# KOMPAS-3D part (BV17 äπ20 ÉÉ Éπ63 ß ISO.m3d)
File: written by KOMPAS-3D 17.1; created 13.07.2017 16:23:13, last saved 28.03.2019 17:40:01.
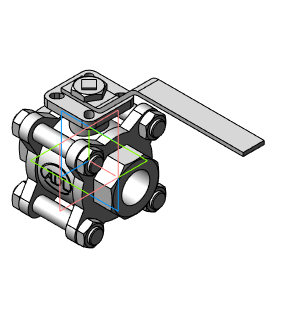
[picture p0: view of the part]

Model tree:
1. Операция без истории:2  (labels: Сталь 20  ГОСТ 1050-88)

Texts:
  DISO1
  DISO2
  BV17 Ду8 1/4" Ру63 с ISO
  BV17 Ду8 СС Ру63 с ISO
  BV17 Ду10 3/8" Ру63 с ISO
  BV17 Ду10 СС Ру63 с ISO
  BV17 Ду15 1/2" Ру63 с ISO
  BV17 Ду15 СС Ру63 с ISO
  BV17 Ду15 ФФ Ру40 с ISO
  BV17 Ду20 3/4" Ру63 с ISO
  BV17 Ду20 СС Ру40 с ISO
  BV17 Ду20 ФФ Ру40 с ISO
  BV17 Ду25 1" Ру63 с ISO
  BV17 Ду25 СС Ру63 с ISO
  BV17 Ду25 ФФ Ру40 с ISO
  BV17 Ду32 1 1/4" Ру63 с ISO
  BV17 Ду32 СС Ру63 с ISO
  BV17 Ду32 ФФ Ру40 с ISO
  BV17 Ду40 1 1/2" Ру63 с ISO
  BV17 Ду40 СС Ру63 с ISO
  BV17 Ду40 ФФ Ру40 с ISO
  BV17 Ду50 2" Ру63 с ISO
  BV17 Ду50 СС Ру63 с ISO
  BV17 Ду50 ФФ Ру40 с ISO
  BV17 Ду65 2 1/2" Ру40 с ISO
  BV17 Ду65 СС Ру40 с ISO
  BV17 Ду65 ФФ Ру40 с ISO
  BV17 Ду80 3" Ру40 с ISO
  BV17 Ду80 СС Ру40 с ISO
  BV17 Ду80 ФФ Ру40 с ISO
  BV17 Ду100 4" Ру40 с ISO
  BV17 Ду100 СС Ру40 с ISO
  BV17 Ду100 ФФ Ру40 с ISO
